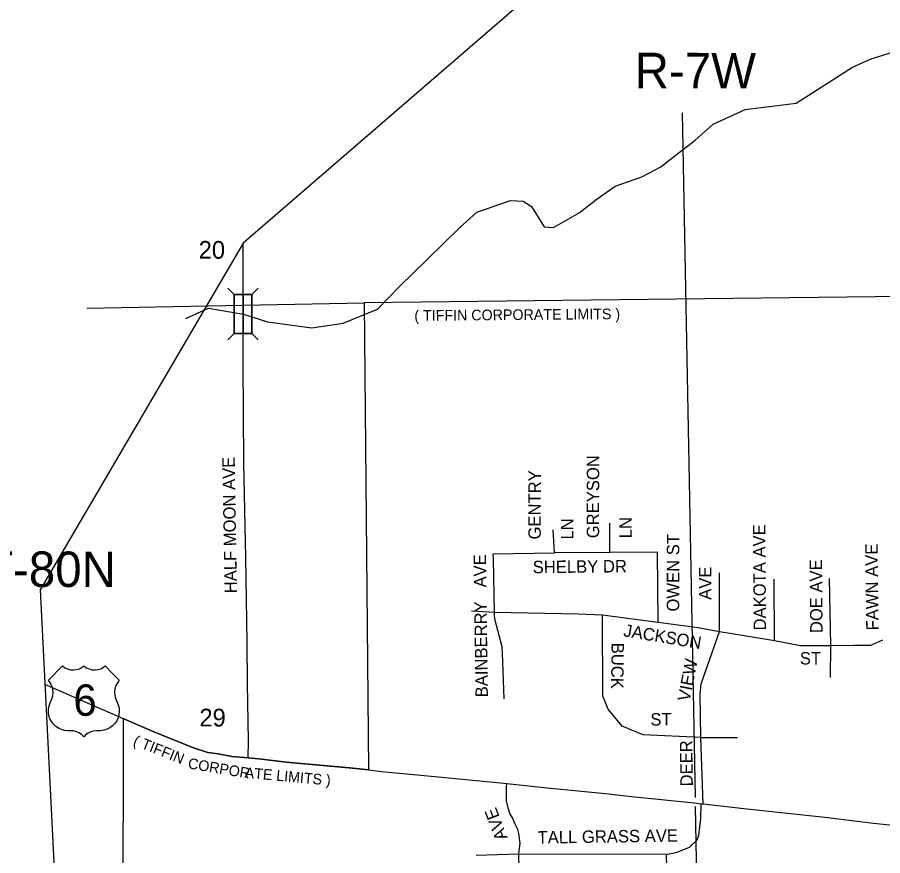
# Model space of a CAD drawing. Extents: x 281.94 to 289.14, y 116.09 to 120.89.
# Drawn here: x 282.9 to 283.875, y 118.797 to 119.742 of the extents above; entities that cross this region are included whole.
import ezdxf

# ---------------------------------------------------------------- set-up
doc = ezdxf.new("R2010")
doc.units = 0
for name, color, linetype in [('tdCiCityStreetCL', 7, 'Continuous'), ('tdCiCityStreetTxt', 7, 'Continuous'), ('tdCiCorpBndry', 7, 'Continuous'), ('tdCiCorpBndryPart', 7, 'Continuous'), ('tdCiCorpBndryTxt', 7, 'Continuous'), ('tdCiHydroRiver', 7, 'Continuous'), ('tdCiMapPltShpe', 7, 'Continuous'), ('tdCiPriCL', 7, 'Continuous'), ('tdCiPriDiv', 7, 'Continuous'), ('tdCiSecCL', 7, 'Continuous'), ('tdCiSecText', 7, 'Continuous'), ('tdCiSectLine', 7, 'Continuous'), ('tdCiSectNmbr', 7, 'Continuous'), ('tdCiSectTwpRng', 7, 'Continuous'), ('tdCiShieldPriUsRte', 7, 'Continuous'), ('tdCiStrucDataSec', 7, 'Continuous')]:
    doc.layers.add(name, color=color, linetype=linetype)

msp = doc.modelspace()

# ---------------------------------------------------------------- linework, layer by layer
at = {"layer": 'tdCiCityStreetCL'}
for points in [[(283.56799, 119.13871), (283.56786, 119.17151)], [(283.50556, 119.13805), (283.50392, 119.16409)], [(283.43791, 119.07133), (283.4368, 119.13123), (283.4365, 119.13693), (283.50556, 119.13805), (283.50556, 119.13805)], [(283.62217, 119.06011), (283.62165, 119.13906), (283.56799, 119.13859), (283.50556, 119.13805)], [(283.50558, 119.13772), (283.50556, 119.13805)], [(283.69119, 119.04964), (283.69128, 119.11575)], [(283.75334, 119.03928), (283.75304, 119.10843)], [(283.81672, 119.03371), (283.8154, 119.10942)], [(283.41201, 119.07268), (283.43791, 119.07133)], [(283.43791, 119.07133), (283.53198, 119.06958), (283.55973, 119.0683)], [(283.44882, 118.97368), (283.44748, 119.0155), (283.44652, 119.03209), (283.43855, 119.06208), (283.43791, 119.06718), (283.43791, 119.07133)], [(283.55973, 119.0683), (283.62217, 119.06011)], [(283.67023, 118.93003), (283.60532, 118.93319), (283.58173, 118.94276), (283.56578, 118.9619), (283.56004, 118.97658), (283.55973, 119.0683)], [(283.62217, 119.06011), (283.62217, 119.06011)], [(283.62217, 119.06011), (283.66736, 119.05417), (283.69119, 119.04964)], [(283.67023, 118.93003), (283.6697, 118.97897), (283.67072, 118.99045), (283.68527, 119.03238), (283.69119, 119.04964)], [(283.69119, 119.04964), (283.71922, 119.04497), (283.75334, 119.03928)], [(283.81672, 119.03371), (283.84261, 119.0341), (283.8616, 119.0341), (283.87514, 119.04026)], [(283.75334, 119.03928), (283.78243, 119.03386), (283.81672, 119.03371)], [(283.81647, 118.9976), (283.81672, 119.03371)], [(283.67023, 118.93003), (283.71166, 118.93003)], [(283.67023, 118.93003), (283.67023, 118.93003)], [(283.67284, 118.85519), (283.67023, 118.93003)], [(283.46515, 118.79873), (283.46688, 118.81096), (283.46528, 118.82181), (283.46401, 118.82643), (283.4613, 118.83217), (283.45827, 118.83935), (283.45508, 118.8443), (283.45364, 118.84908), (283.45125, 118.85849), (283.45157, 118.87429), (283.45198, 118.87812)], [(283.63167, 118.79872), (283.63309, 118.79872), (283.64361, 118.80095), (283.65754, 118.80643), (283.66587, 118.81446), (283.66615, 118.81474), (283.66809, 118.81988), (283.67016, 118.83866), (283.67073, 118.85543)], [(283.4171, 118.7975), (283.46515, 118.79873)], [(283.46515, 118.79873), (283.46515, 118.79873)], [(283.46515, 118.79873), (283.63167, 118.79872)], [(283.46515, 118.79873), (283.46515, 118.79873)], [(283.46723, 118.71617), (283.46515, 118.79873)], [(283.63167, 118.79872), (283.63167, 118.79873)], [(283.63361, 118.71987), (283.63167, 118.79872)]]:
    msp.add_lwpolyline(points, dxfattribs=at)
at = {"layer": 'tdCiCorpBndry'}
msp.add_lwpolyline([(283.90096, 119.92932), (283.90847, 119.67735), (283.94087, 119.67764), (284.15422, 119.67956), (284.15429, 119.6768), (284.15453, 119.67179), (284.15522, 119.64041), (284.15429, 119.59631), (284.15595, 119.43005), (284.1225, 119.42966), (283.2912, 119.42007), (283.29586, 118.89344), (283.2751, 118.89569), (283.20343, 118.90239), (283.17567, 118.90564), (283.16064, 118.90695), (283.14216, 118.90855), (283.12665, 118.91148), (283.11496, 118.91327), (283.09906, 118.91855), (283.07551, 118.92788), (283.05148, 118.93762), (283.01972, 118.95139), (283.01903, 118.48418)], dxfattribs=at)
at = {"layer": 'tdCiCorpBndryPart'}
for points in [[(284.15449, 119.5761), (284.15595, 119.43005), (284.1225, 119.42966), (283.2912, 119.42007), (283.29586, 118.89344), (283.29586, 118.89344)], [(283.01972, 118.95139), (283.01903, 118.48418), (284.03091, 118.53597), (284.03224, 118.4252), (284.17571, 118.42646)]]:
    msp.add_lwpolyline(points, dxfattribs=at)
at = {"layer": 'tdCiHydroRiver'}
msp.add_lwpolyline([(283.09011, 119.40226), (283.11563, 119.41404), (283.15516, 119.40724), (283.18237, 119.39834), (283.23211, 119.39179), (283.26744, 119.39703), (283.30605, 119.41273), (283.33091, 119.43825), (283.36298, 119.46966), (283.39831, 119.50434), (283.41794, 119.52201), (283.4559, 119.5351), (283.47029, 119.53444), (283.47945, 119.52855), (283.47945, 119.52855), (283.49385, 119.50565), (283.50432, 119.505), (283.53311, 119.52136), (283.55339, 119.53706), (283.57368, 119.55146), (283.60378, 119.56193), (283.62537, 119.57305), (283.64108, 119.58548), (283.66398, 119.60315), (283.68427, 119.62147), (283.72025, 119.63783), (283.77784, 119.64503), (283.84131, 119.6856), (283.86225, 119.69476), (283.90633, 119.70873)], dxfattribs=at)
at = {"layer": 'tdCiMapPltShpe'}
for points in [[(284.09767, 120.22261), (283.90287, 120.13391), (283.15477, 119.48709)], [(283.15477, 119.48709), (282.92633, 119.09647), (282.95826, 118.46016)]]:
    msp.add_lwpolyline(points, dxfattribs=at)
at = {"layer": 'tdCiPriCL'}
msp.add_lwpolyline([(282.93167, 118.98991), (282.93363, 118.98908), (282.98184, 118.96781), (283.01971, 118.95139), (283.05148, 118.93762), (283.07551, 118.92788), (283.09906, 118.91855), (283.11496, 118.91327), (283.12665, 118.91148), (283.14216, 118.90855), (283.16064, 118.90695), (283.17567, 118.90564), (283.20343, 118.90239), (283.27378, 118.89583), (283.29586, 118.89344), (283.31058, 118.89184), (283.37071, 118.88624), (283.44824, 118.87853), (283.45124, 118.8782), (283.45198, 118.87812), (283.501, 118.87285), (283.53226, 118.86974), (283.56626, 118.86635), (283.59207, 118.86343), (283.66318, 118.85629), (283.67073, 118.85543), (283.67284, 118.85519), (283.71869, 118.84996), (283.81009, 118.84022), (283.86496, 118.8334), (283.94077, 118.82561)], dxfattribs=at)
at = {"layer": 'tdCiPriDiv'}
msp.add_lwpolyline([(282.93167, 118.98991), (282.93363, 118.98908), (282.98184, 118.96781), (283.01971, 118.95139), (283.05148, 118.93762), (283.07551, 118.92788), (283.09906, 118.91855), (283.11496, 118.91327), (283.12665, 118.91148), (283.14216, 118.90855), (283.16064, 118.90695), (283.17567, 118.90564), (283.20343, 118.90239), (283.27378, 118.89583), (283.29586, 118.89344), (283.31058, 118.89184), (283.37071, 118.88624), (283.44824, 118.87853), (283.45124, 118.8782), (283.45198, 118.87812), (283.501, 118.87285), (283.53226, 118.86974), (283.56626, 118.86635), (283.59207, 118.86343), (283.66318, 118.85629), (283.67073, 118.85543), (283.67284, 118.85519), (283.71869, 118.84996), (283.81009, 118.84022), (283.86496, 118.8334), (283.94077, 118.82561)], dxfattribs=at)
at = {"layer": 'tdCiSecCL'}
msp.add_lwpolyline([(283.16064, 118.90695), (283.1607, 118.9264), (283.15968, 118.99037), (283.15918, 119.03747), (283.15795, 119.13315), (283.15573, 119.23919), (283.15475, 119.35214), (283.15475, 119.40348), (283.15475, 119.41201), (283.15475, 119.41306), (283.15475, 119.41798), (283.15475, 119.48185), (283.15473, 119.48703)], dxfattribs=at)
at = {"layer": 'tdCiSectLine'}
for p, q in [((283.66414, 118.86228), (283.64971, 119.63399)), ((282.97892, 119.41387), (283.2912, 119.42007))]:
    msp.add_line(p, q, dxfattribs=at)
msp.add_lwpolyline([(283.68631, 117.90107), (283.67236, 118.4278), (283.66414, 118.85237)], dxfattribs=at)
at = {"layer": 'tdCiShieldPriUsRte'}
msp.add_lwpolyline([(283.00736, 119.0027), (283.01528, 118.99478), (283.01313, 118.99177), (283.01151, 118.98845), (283.01047, 118.98491), (283.01004, 118.98124), (283.01023, 118.97755), (283.01103, 118.97394), (283.01242, 118.97052), (283.01411, 118.96669), (283.01499, 118.9631), (283.01526, 118.95942), (283.01491, 118.95574), (283.01395, 118.95217), (283.01241, 118.94881), (283.01033, 118.94576), (283.00776, 118.9431), (283.00479, 118.9409), (283.00149, 118.93924), (282.99796, 118.93814), (282.9943, 118.93765), (282.98979, 118.93763), (282.98641, 118.93732), (282.98314, 118.9364), (282.9801, 118.9349), (282.97737, 118.93288), (282.97534, 118.93074), (282.97298, 118.93317), (282.97021, 118.93513), (282.96712, 118.93656), (282.96384, 118.9374), (282.9609, 118.93763), (282.95746, 118.93763), (282.95378, 118.93794), (282.9502, 118.93886), (282.94682, 118.94036), (282.94375, 118.94241), (282.94106, 118.94495), (282.93883, 118.94789), (282.93713, 118.95117), (282.93599, 118.95469), (282.93546, 118.95835), (282.93555, 118.96204), (282.93626, 118.96567), (282.93756, 118.96912), (282.93951, 118.97347), (282.94039, 118.97706), (282.94066, 118.98075), (282.94031, 118.98442), (282.93935, 118.98799), (282.93781, 118.99135), (282.93541, 118.99478), (282.95124, 119.01062), (282.95402, 119.00866), (282.9571, 119.00724), (282.96039, 119.00641), (282.96378, 119.00619), (282.96715, 119.00659), (282.97039, 119.00759), (282.97339, 119.00917), (282.97534, 119.01062), (282.97812, 119.00866), (282.9812, 119.00724), (282.98449, 119.00641), (282.988, 119.00617), (282.99125, 119.00659), (282.99449, 119.00759), (282.99749, 119.00917), (282.99944, 119.01062)], close=True, dxfattribs=at)
at = {"layer": 'tdCiStrucDataSec'}
for points in [[(283.16475, 119.42937), (283.15475, 119.42937), (283.14475, 119.42937), (283.13767, 119.43644)], [(283.16475, 119.38537), (283.16475, 119.42937), (283.17182, 119.43644)], [(283.14475, 119.42937), (283.14475, 119.38537), (283.13767, 119.3783)], [(283.15475, 119.42937), (283.15475, 119.40737), (283.15475, 119.38537)], [(283.14475, 119.38537), (283.15475, 119.38537), (283.16475, 119.38537), (283.17182, 119.3783)]]:
    msp.add_lwpolyline(points, dxfattribs=at)
msp.add_lwpolyline([(283.16475, 119.42937), (283.16475, 119.38537), (283.14475, 119.38537), (283.14475, 119.42937)], close=True, dxfattribs=at)

# ---------------------------------------------------------------- texts
at = {"layer": 'tdCiCityStreetTxt'}
for s, rotation, p in [('GREYSON', 89.92888, (283.55574, 119.15462)), ('GENTRY', 89.92888, (283.49003, 119.15321)), ('LN', 89.92888, (283.59245, 119.15458)), ('LN', 89.92888, (283.52673, 119.15316)), ('DAKOTA AVE', 90.42008, (283.74378, 119.05074)), ('OWEN ST', 89.92888, (283.64593, 119.07199)), ('FAWN AVE', 90.71846, (283.87059, 119.05081)), ('BAINBERRY   AVE', 90.80642, (283.43054, 118.97542)), ('SHELBY DR', 0.52774, (283.48099, 119.11522)), ('DOE AVE', 90.42008, (283.80746, 119.04768)), ('AVE', 89.92888, (283.68222, 119.08522)), ('JACKSON', 350.53741, (283.58248, 119.04421)), ('BUCK', 269.35957, (283.56974, 119.03694)), ('ST', 359.76006, (283.78181, 119.01236)), ('VIEW', 79.01299, (283.65766, 118.97)), ('ST', 0.52774, (283.61355, 118.94343)), ('DEER', 90.80642, (283.66137, 118.87498)), ('AVE', 110.80961, (283.45275, 118.81726)), ('TALL GRASS AVE', 0.80642, (283.48649, 118.81042))]:
    msp.add_text(s, height=0.014, rotation=rotation, dxfattribs=at).set_placement(p)
at = {"layer": 'tdCiCorpBndryTxt'}
for s, rotation, p in [('( TIFFIN CORPORATE LIMITS )', 0.48302, (283.34765, 119.39962)), ('( TIFFIN', 338.25821, (283.03004, 118.92194)), ('CORPOR', 350.41941, (283.09204, 118.8953)), ('ATE LIMITS )', 354.78531, (283.15617, 118.88468))]:
    msp.add_text(s, height=0.012, rotation=rotation, dxfattribs=at).set_placement(p)
at = {"layer": 'tdCiSecText'}
msp.add_text('HALF MOON AVE', height=0.014, rotation=90.97356, dxfattribs=at).set_placement((283.14791, 119.09268))
at = {"layer": 'tdCiSectNmbr'}
for s, p in [('20', (283.10469, 119.46968)), ('29', (283.10547, 118.94249))]:
    msp.add_text(s, height=0.02, rotation=359.87667, dxfattribs=at).set_placement(p)
at = {"layer": 'tdCiSectTwpRng'}
for s, rotation, p in [('R-7W', 359.87709, (283.59571, 119.66186)), ('T-80N', 359.87653, (282.86288, 119.09983))]:
    msp.add_text(s, height=0.04, rotation=rotation, dxfattribs=at).set_placement(p)
at = {"layer": 'tdCiShieldPriUsRte'}
msp.add_text('6', height=0.03541, dxfattribs=at).set_placement((282.96355, 118.9545))

doc.saveas('drawing.dxf')
